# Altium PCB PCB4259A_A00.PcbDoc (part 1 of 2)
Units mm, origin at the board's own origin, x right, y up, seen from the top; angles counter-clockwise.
Board outline 30 x 45 mm, 4 copper layers (Top Layer, Signal Layer 2, Signal Layer 3, Bottom Layer), stack 1.606 mm thick; 90 components, 88 nets, 336 pads, 378 vias.
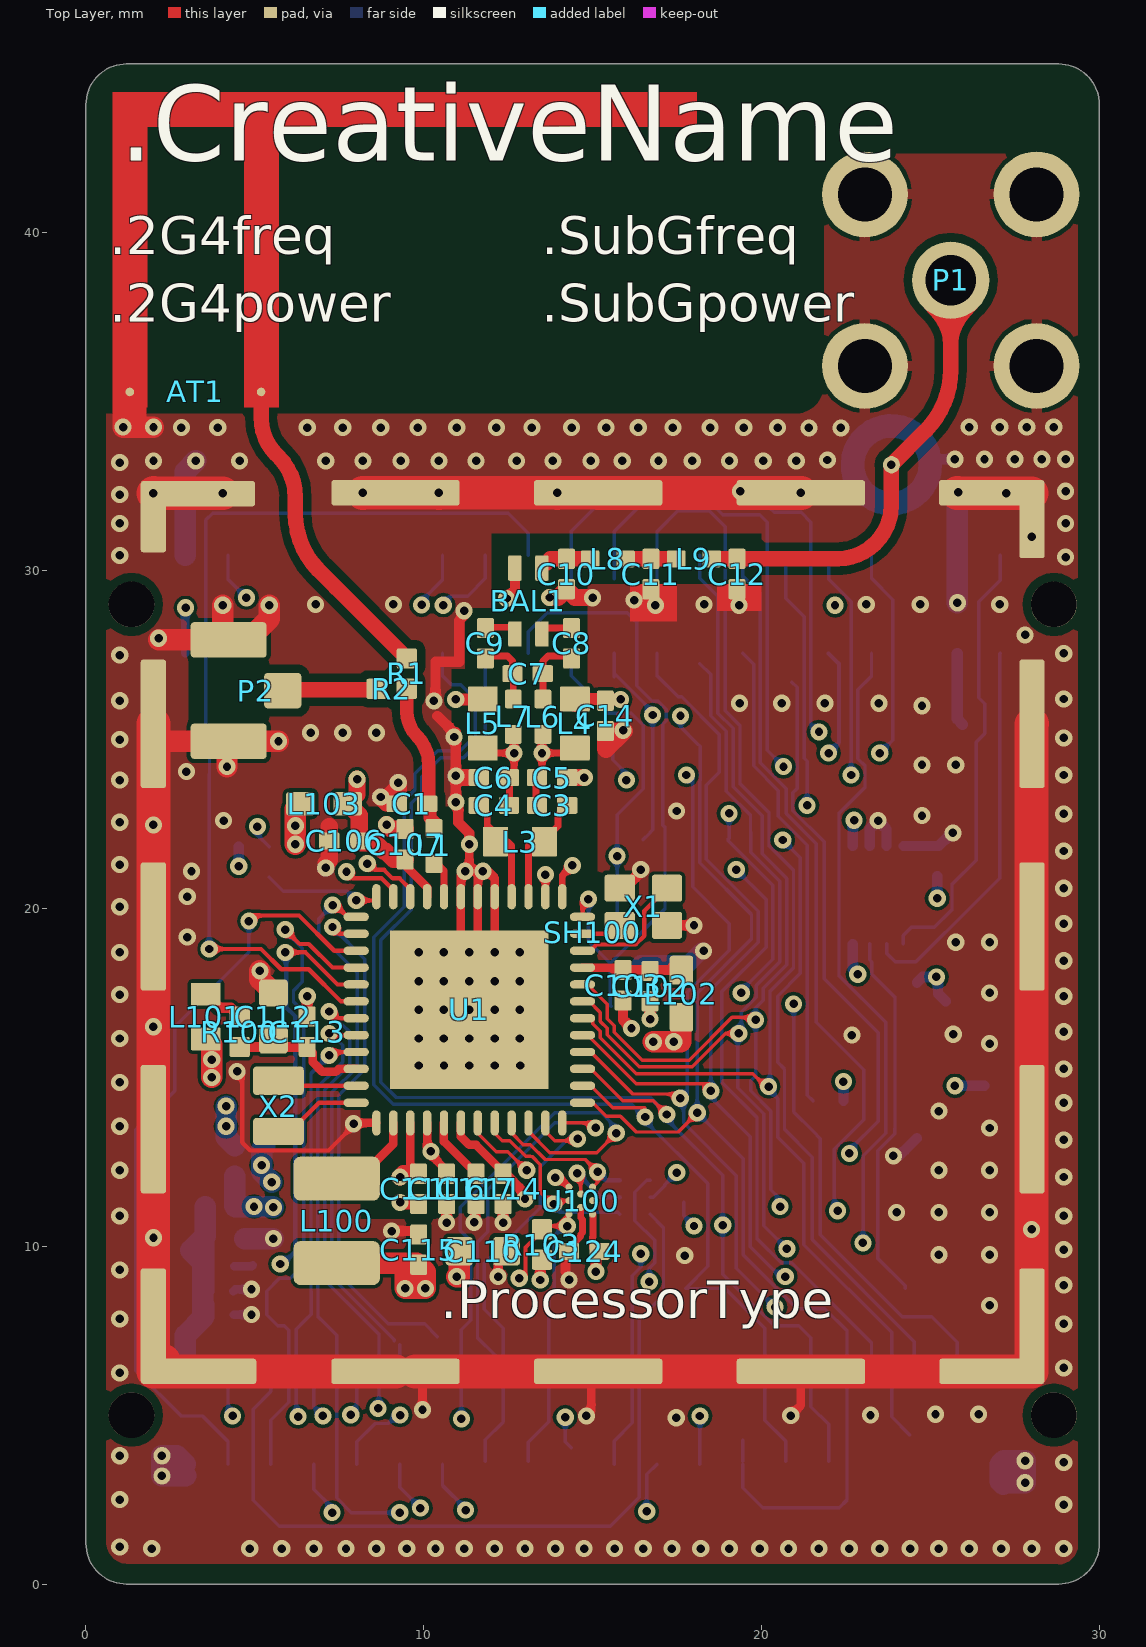
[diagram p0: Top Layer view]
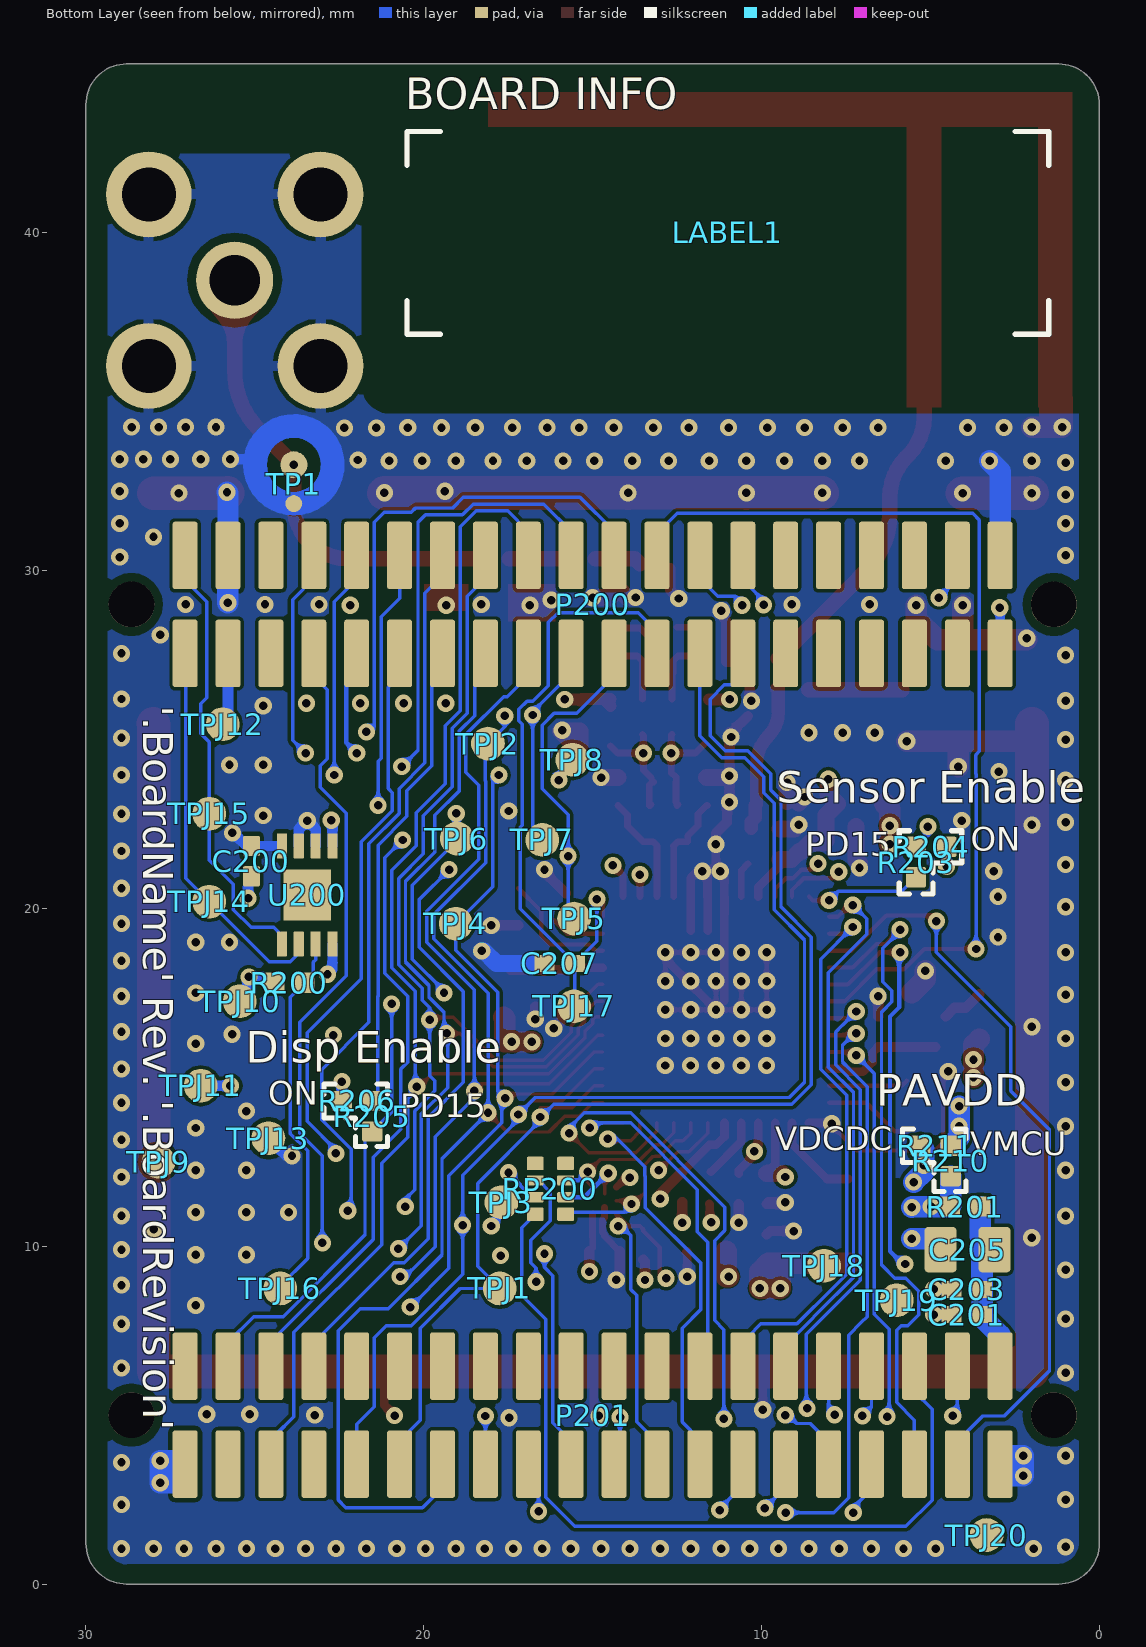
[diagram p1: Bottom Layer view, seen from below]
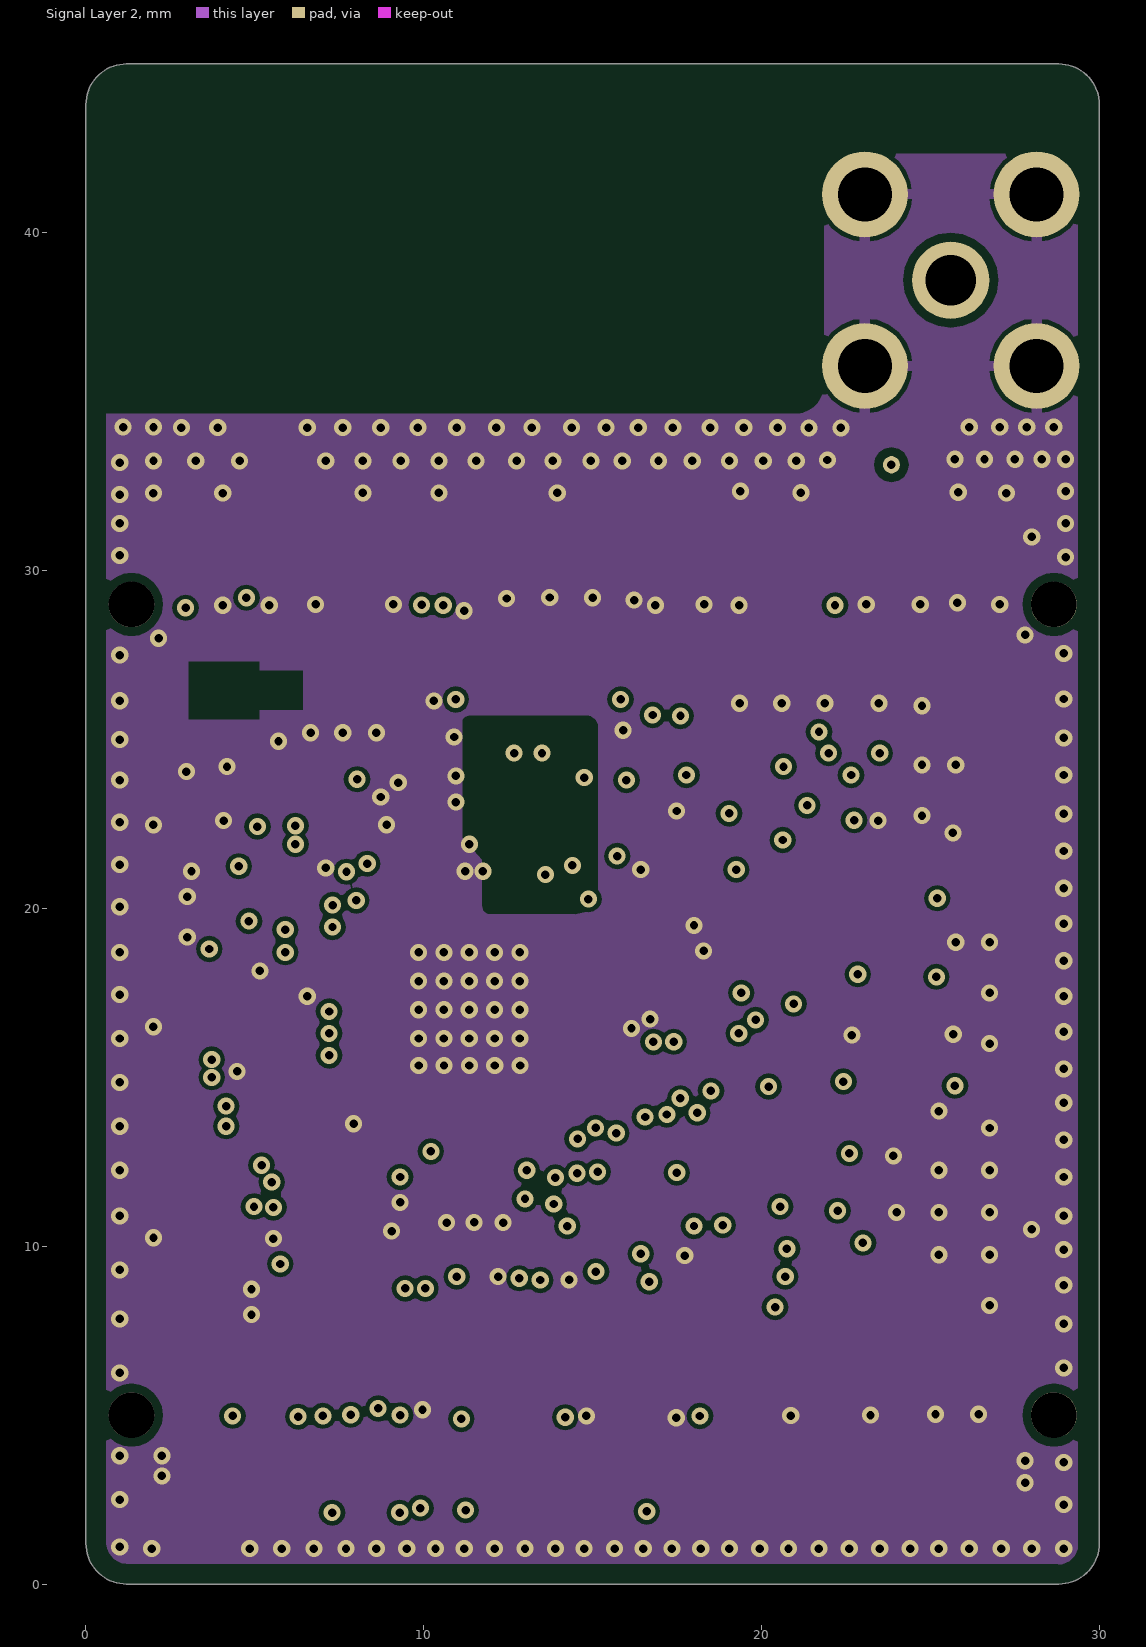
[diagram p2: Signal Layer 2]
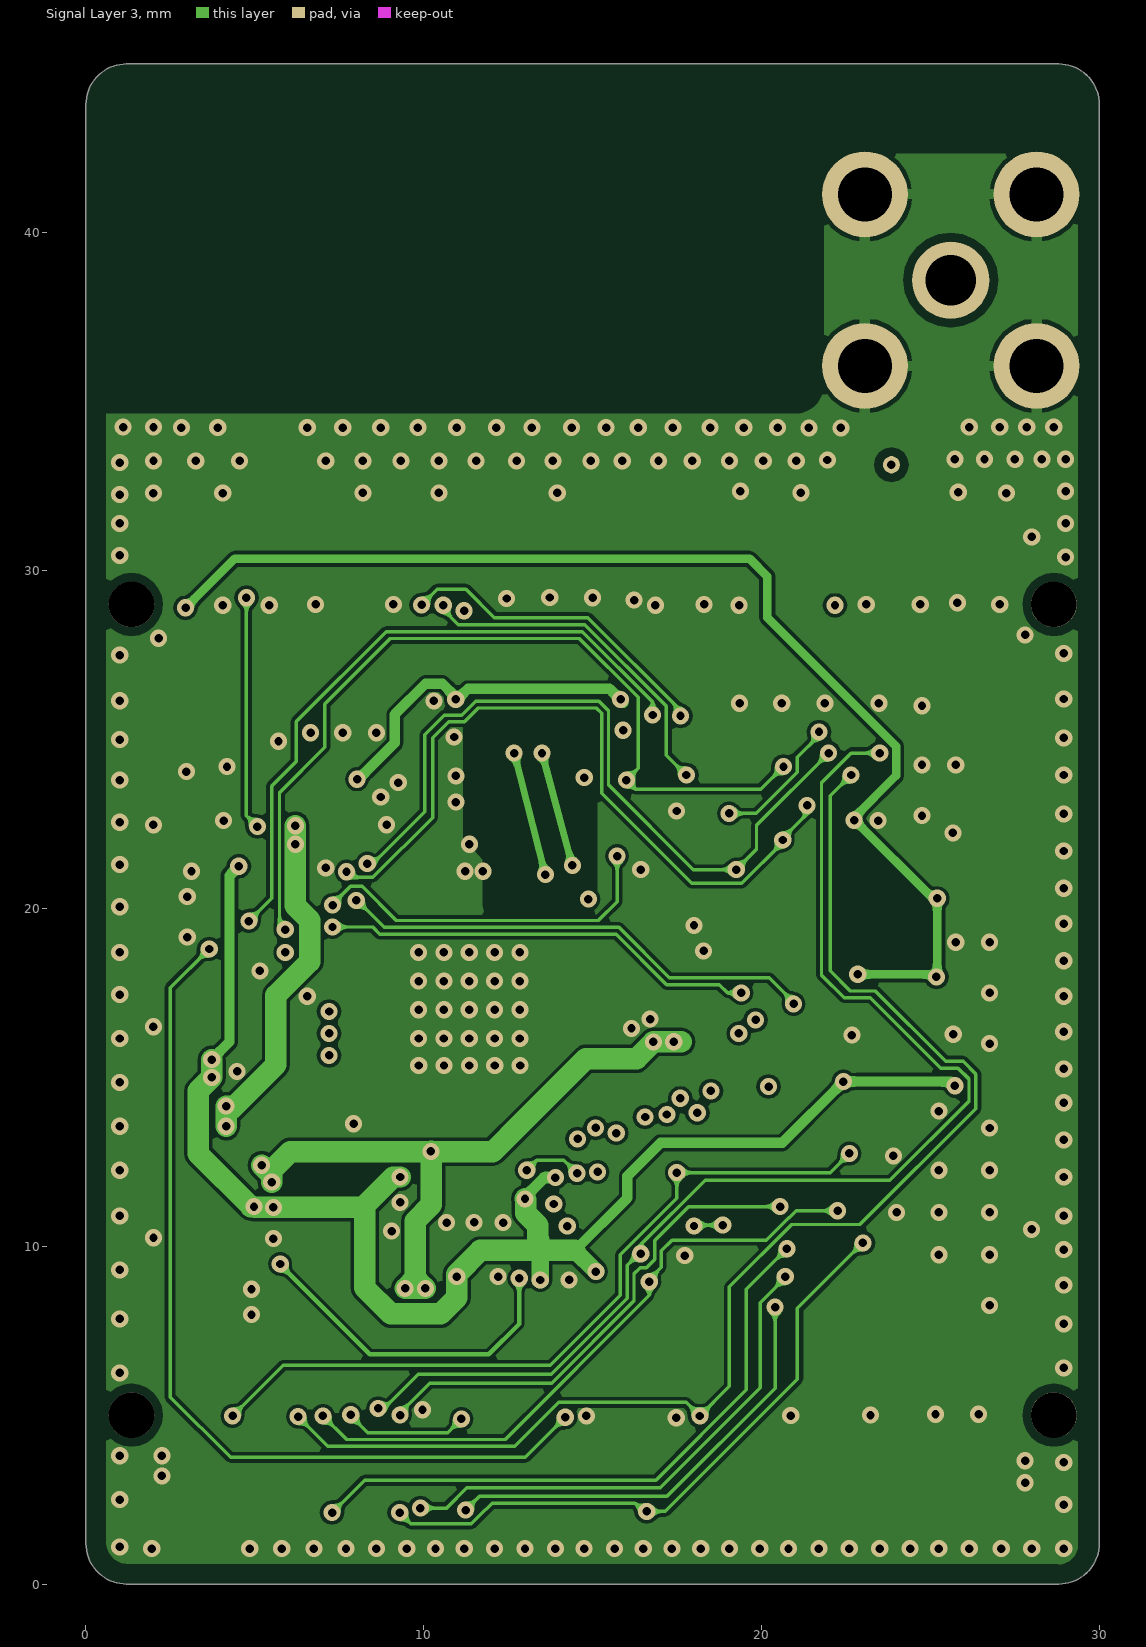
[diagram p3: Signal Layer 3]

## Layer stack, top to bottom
Top Solder: solder mask 0.01, Solder Resist, Dk 3.5
Top Layer: signal copper 0.035
Dielectric 1: core 0.3, FR-4, Dk 4.2
Signal Layer 2: signal copper 0.018
Dielectric 3: prepreg 0.9, Dk 4.2
Signal Layer 3: signal copper 0.018
Dielectric 2: core 0.3, FR-4, Dk 4.2
Bottom Layer: signal copper 0.035
Bottom Solder: solder mask 0.01, Solder Resist, Dk 3.5

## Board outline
0,1.2 ccw(c1.2,1.2) 1.2,0 28.8,0 ccw(c28.8,1.2) 30,1.2 30,43.8 ccw(c28.8,43.8) 28.8,45 1.2,45 ccw(c1.2,43.8) 0,43.8

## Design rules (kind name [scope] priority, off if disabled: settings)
Clearance Clearance_to_Holes [InPadClass('NPTH')] p1: gap=0.254
Clearance Clearance_50Ohm [InNetClass('50Ohm') or InNet('50R_*')] p2: gap=0.25
Clearance Clerance_Polygon_GND3 [InNamedPolygon('GND_3')] p3: gap=0.127
Clearance Clerance_Polygon_GND2 [InNamedPolygon('GND_2')] p4: gap=0.127
Clearance Clerance_Polygon_GND1 [InNamedPolygon('GND_L2')] p5: gap=0.127
Clearance Clerance_Polygon_GND4 [InNamedPolygon('GND_4')] p6: gap=0.127
Clearance Clearance_General [All] p7: gap=0.102
ComponentClearance [All] p1: gap=0.2 collisioncheckmode=3 verticalgap=0.254 showdistances=FALSE
HoleToHoleClearance HoleToHoleClearance_ANT1toPAD [Incomponent ('ANT1') vs ISpad] p1: gap=0 allowstackedmicrovias=TRUE
HoleToHoleClearance HoleToHoleClearance_U1toVIA_1 [InComponent ('U1') vs IsVia] p2: gap=0 allowstackedmicrovias=TRUE
HoleToHoleClearance [All] p3: gap=0.254 allowstackedmicrovias=TRUE
MinimumSolderMaskSliver [All] p1: minsoldermaskwidth=0.102
PolygonConnect PolygonConnect_SH100 [InComponent('SH100')] p1: connectstyle=Direct reliefconductorwidth=0.254 reliefentries=4 polygonreliefangle="90 Angle" airgapwidth=0.127
PolygonConnect PolygonConnect_P1 [InComponent('P1')] p2: connectstyle=Relief reliefconductorwidth=0.305 reliefentries=4 polygonreliefangle="90 Angle" airgapwidth=0.127
PolygonConnect Polygon_VIA_Connect [IsVia] p3: connectstyle=Direct reliefconductorwidth=0.254 reliefentries=4 polygonreliefangle="90 Angle" airgapwidth=0.254
PolygonConnect PolygonConnect_General [All] p4: connectstyle=NoConnect reliefconductorwidth=0.254 reliefentries=4 polygonreliefangle="90 Angle" airgapwidth=0.127
RoutingVias [All] p1: holewidth=0.25 width=0.508 viastyle="Through Hole" minholewidth=0.25 minwidth=0.508 maxholewidth=1 maxwidth=1.5
SilkToSilkClearance [All] p1: silktosilkclearance=0.102
SilkToSolderMaskClearance [IsPad] p1: minsilkscreentomaskgap=0.102 clearancetoexposedcopper=TRUE
SolderMaskExpansion [All] p1: expansion=0.051
Width [All] p1: maxlimit=5.08 minlimit=0.102 preferedwidth=0.127
25 further rules are at their usual default settings.

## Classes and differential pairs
pad class NPTH: P200-M1 P200-M2 P201-M1 P201-M2

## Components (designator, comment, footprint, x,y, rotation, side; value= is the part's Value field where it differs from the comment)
AT1 "INVERTED_F" ANT_INV_F_2.4_GHZ_17.3MM_MIR 0.79,34.84 r0 top locked net-tie
BAL1 "ATB2012-50011" TDK_ATB2012 13.1,29.1 r270 top
C1 "1P5" C0402_L 9.65,23.1 r0 top
C3 "1P6" C0402_L 13.8,23.05 r0 top
C4 "1P6" C0402_L 12.075,23.05 r180 top
C5 "Unused" C0402_L 13.8,23.875 r0 top
C6 "Unused" C0402_L 12.075,23.875 r180 top
C7 "4P7" C0402_L 13.075,26.95 r180 top
C8 "270P" C0402_L 14.375,27.85 r270 top
C9 "270P" C0402_L 11.825,27.85 r270 top
C10 "6P2" C0402_L 14.225,29.9 r270 top
C11 "11P" C0402_L 16.725,29.9 r270 top
C12 "5P6" C0402_L 19.275,29.9 r270 top
C14 "270P" C0402_L 15.375,25.7 r270 top
C102 "100P" C0402_L 16.7,17.7 r270 top
C103 "10P" C0402_L 15.9,17.725 r270 top
C106 "220N" C0402_L 7.65,22 r180 top
C107 "10P" C0402_L 9.45,21.9 r90 top
C110 "10U" C0603_L 11.75,9.85 r0 top
C111 "1U" C0402_L 9.848,11.7 r270 top
C112 "10U" C0603_L 5.55,16.8 r90 top
C113 "10N" C0402_L 6.548,16.35 r90 top
C114 "1U" C0402_L 12.35,11.7 r270 top
C115 "4U7" C0402_L 9.85,9.9 r90 top
C116 "100N" C0402_L 10.675,11.7 r270 top
C117 "1U" C0402_L 11.55,11.7 r270 top
C124 "100N" C0402_L 14.75,9.85 r180 top
C200 "100N" C0402_L 25.1,21.4 r90 bottom
C201 "100N" C0402_L 3.925,7.975 r0 bottom
C203 "100N" C0402_L 3.925,8.725 r0 bottom
C205 "10U" C0805_L 3.9,9.9 r0 bottom
C207 "100N" C0402_L 15.975,18.375 r0 bottom
Designator16 "Comment" PCB_SPEC_4_LAYER -81.197,100.739 r0 top
L1 "1N9" COIL_0402_L 10.3,21.85 r90 top
L3 "75N" COIL_0603_L 12.85,21.975 r180 top
L4 "470N" COIL_0603_L 14.475,25.475 r270 top
L5 "470N" COIL_0603_L 11.75,25.475 r270 top
L6 "18N" COIL_0402_L 13.525,25.675 r270 top
L7 "18N" COIL_0402_L 12.65,25.675 r270 top
L8 "24N" COIL_0402_L 15.45,30.35 r180 top
L9 "24N" COIL_0402_L 18,30.35 r180 top
L100 "4U7" COIL_MUR_LQH3NP_1212 7.425,10.75 r270 top
L101 "CBF102WB" WURTH_CBF_0603 3.55,16.8 r90 top
L102 "BLM18AG601SN1" COIL_MUR_BLM18_0603 17.628,17.475 r90 top
L103 "BLM18AG601SN1" COIL_MUR_BLM18_0603 7.05,23.1 r0 top
LABEL1 "Comment" LABEL_4CORNERS_19.0X6.0 11,40 r180 bottom
P1 "SMA" TE_SMA_TH_1814832 25.6,38.6 r0 top locked
P2 "U.FL" HIROSE_U.FL-R-SMT-1 4.225,26.45 r270 top
P200 "SOCKET_2X20_1.27MM_SMD" SAM_SFC-120-T2-D-A-2X20_SNUM 15,29 r0 bottom locked
P201 "SOCKET_2X20_1.27MM_SMD" SAM_SFC-120-T2-D-A-2X20_SNUM 15,5 r0 bottom locked
R1 "0R" R0402_L 9.5,26.95 r90 top
R2 "0R" R0402_L 9.05,26.5 r180 top
R100 "1R" R0402_L 4.55,16.35 r270 top
R103 "330K" R0402_L 13.5,10.05 r90 top
R200 "10K" R0402_L 23.978,17.8 r0 bottom
R201 "0R" R0402_L 3.975,11.175 r0 bottom
R203 "0R" R0402_L 5.425,21.375 r90 bottom
R204 "0R" R0402_L 4.975,21.825 r0 bottom
R205 "0R" R0402_L 21.525,13.85 r90 bottom
R206 "0R" R0402_L 21.975,14.3 r180 bottom
R210 "0R" R0402_L 4.4,12.525 r270 bottom
R211 "0R" R0402_L 4.85,12.975 r0 bottom
RP200 "100R" RES_MNR04-8 16.25,11.7 r90 bottom
SH100 "RF_SHIELD_FRAME_BMI-S-203-F" RF_SHIELD_FRAME_BMI-S-203-F_PCB4100 15,19.3 r0 top locked
TP1 "RF_TEST_POINT" "TP_INGUN_50_OHM_CLOSED openvia" 23.845,33.135 r180 bottom locked
TPJ1 "TPJ_SMD" TP_1.0_SMD 17.75,8.75 r90 bottom locked
TPJ2 "TPJ_SMD" TP_1.0_SMD 18.1,24.88 r90 bottom locked
TPJ3 "TPJ_SMD" TP_1.0_SMD 17.7,11.3 r90 bottom locked
TPJ4 "TPJ_SMD" TP_1.0_SMD 19.05,19.55 r90 bottom locked
TPJ5 "TPJ_SMD" TP_1.0_SMD 15.55,19.7 r90 bottom locked
TPJ6 "TPJ_SMD" TP_1.0_SMD 19.02,22.07 r90 bottom locked
TPJ7 "TPJ_SMD" TP_1.0_SMD 16.49,22.03 r90 bottom locked
TPJ8 "TPJ_SMD" TP_1.0_SMD 15.6,24.4 r90 bottom locked
TPJ9 "TPJ_SMD" TP_1.0_SMD 27.85,12.5 r90 bottom locked
TPJ10 "TPJ_SMD" TP_1.0_SMD 25.45,17.25 r90 bottom locked
TPJ11 "TPJ_SMD" TP_1.0_SMD 26.6,14.75 r90 bottom locked
TPJ12 "TPJ_SMD" TP_1.0_SMD 25.95,25.45 r90 bottom locked
TPJ13 "TPJ_SMD" TP_1.0_SMD 24.6,13.2 r90 bottom locked
TPJ14 "TPJ_SMD" TP_1.0_SMD 26.35,20.2 r90 bottom locked
TPJ15 "TPJ_SMD" TP_1.0_SMD 26.35,22.8 r90 bottom locked
TPJ16 "TPJ_SMD" TP_1.0_SMD 24.25,8.75 r90 bottom locked
TPJ17 "TPJ_SMD" TP_1.0_SMD 15.55,17.1 r90 bottom locked
TPJ18 "TPJ_SMD" TP_1.0_SMD 8.15,9.42 r90 bottom locked
TPJ19 "TPJ_SMD" TP_1.0_SMD 6,8.4 r90 bottom locked
TPJ20 "TPJ_SMD" TP_1.0_SMD 3.34,1.45 r90 bottom locked
U1 "EFR32FG14P233F256GM48" QFN48_M050_SQ7.0_EP_SL_L 11.35,17 r180 top
U100 "MX25R8035F" BGA8_M040_1.24x1.75_WLCSP 14.648,11.35 r180 top
U200 "24AA024" TDFN8_M050_2.0x3.0_EP 23.45,20.4 r0 bottom
X1 "38.400 MHz" X_SSS_DSX211SH_2.05X1.65-4 16.5,20.05 r0 top
X2 "32.768 kHz" X_MCS_CM8V-T1A 5.698,14.15 r90 top

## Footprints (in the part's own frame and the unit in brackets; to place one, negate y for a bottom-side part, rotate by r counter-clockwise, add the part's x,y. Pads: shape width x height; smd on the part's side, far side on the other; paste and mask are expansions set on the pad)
ANT_INV_F_2.4_GHZ_17.3MM_MIR [mil] "Antenna inverted F, 2.4 GHz, 17.3 mm (MIR)"
  round 10 smd paste-5 mask-5: 1(173,17.72) 2(20.01,17.72)
  Top Layer region: 0.36,367.2 681,367.2 681,327.07 193.36,327.07 193.36,0 153.36,0 153.36,327.07 40.36,327.07 40.36,0 20.36,0 0.36,0
BGA8_M040_1.24x1.75_WLCSP [mm] "BGA, 8 pin. U100"
  round 0.21 smd mask+0.051: A1(-0.35,0.4) A3(0.35,0.4) B2(0,0.2) C1(-0.35,0) C3(0.35,0) D2(0,-0.2) E1(-0.35,-0.4) E3(0.35,-0.4)
  body extent -0.63,-0.89 0.63,0.88, height 0.52
C0402_L [mm] "Chip Capacitor, 2-Leads, Body 1.0x0.5mm, IPC High Density"
  rrect20% 0.6x0.5 smd mask+0.051: 1(-0.45,0) 2(0.45,0)
  body extent -0.5,-0.25 0.5,0.25, height 0.6
C0603_L [mm] "Capacitor, 0603, High Density (C)"
  rrect25% 0.8x0.85 smd: 1(-0.7,0) 2(0.7,0)
  body extent -0.88,-0.48 0.87,0.48, height 0.95
C0805_L [mm] "Capacitor, 0805"
  rrect25% 0.95x1.35 smd: 1(-0.8,0) 2(0.8,0)
  body extent -1.1,-0.72 1.1,0.72, height 1.45
COIL_0402_L [mm] "COIL_0402_L"
  rrect20% 0.55x0.5 smd mask+0.051: 1(-0.525,0) 2(0.525,0)
  body extent -0.5,-0.25 0.5,0.25, height 0.6
COIL_0603_L [mm] "COIL 0603_L (= L0603_0.8_L)"
  rrect10% 0.75x0.88 smd: 1(-0.725,0) 2(0.725,0)
  body extent -0.8,-0.4 0.8,0.4, height 0.8
COIL_MUR_BLM18_0603 [mm] "COIL_MUR_BLM18P_0603"
  rrect25% 0.85x0.7 smd mask+0.051: 1(-0.7,0) 2(0.7,0)
  body extent -0.88,-0.48 0.87,0.48, height 0.95
COIL_MUR_LQH3NP_1212 [mm] "COIL_MUR_LQH3NP_1212"
  rrect30% 1.3x2.55 smd mask+0.051: 1(-1.25,0) 2(1.25,0)
  body extent -1.6,-1.6 1.6,1.6, height 1.5
HIROSE_U.FL-R-SMT-1 [mm] "COAX_HIROSE_U.FL_CL331-0471"
  rrect20% 1.05x1.1 smd mask+0.051: 1(0,1.6)
  rrect20% 1.05x2.25 smd mask+0.051: 2(-1.5,0) 3(1.5,0)
  Top Layer pour cut-out: -0.85,0.9 0.85,0.9 0.85,0.9 0.85,-1.2 -0.85,-1.2 -0.85,-1.2
  body extent -1.3,-1.55 1.3,1.3, height 0.9
LABEL_4CORNERS_19.0X6.0 [mm]
  silkscreen extent -9.5,-3 9.5,3
PCB_SPEC_4_LAYER [mm]
QFN48_M050_SQ7.0_EP_SL_L [mm] "QFN48_M050_SQ7.0_EP, SiLabs, High Density (C)"
  oval 0.75x0.25 smd: 1(-3.35,2.75) 2(-3.35,2.25) 3(-3.35,1.75) 4(-3.35,1.25) 5(-3.35,0.75) 6(-3.35,0.25) 7(-3.35,-0.25) 8(-3.35,-0.75) 9(-3.35,-1.25) 10(-3.35,-1.75) 11(-3.35,-2.25) 12(-3.35,-2.75) 25(3.35,-2.75) 26(3.35,-2.25) 27(3.35,-1.75) 28(3.35,-1.25) 29(3.35,-0.75) 30(3.35,-0.25) 31(3.35,0.25) 32(3.35,0.75) 33(3.35,1.25) 34(3.35,1.75) 35(3.35,2.25) 36(3.35,2.75)
  oval 0.25x0.75 smd: 13(-2.75,-3.35) 14(-2.25,-3.35) 15(-1.75,-3.35) 16(-1.25,-3.35) 17(-0.75,-3.35) 18(-0.25,-3.35) 19(0.25,-3.35) 20(0.75,-3.35) 21(1.25,-3.35) 22(1.75,-3.35) 23(2.25,-3.35) 24(2.75,-3.35) 37(2.75,3.35) 38(2.25,3.35) 39(1.75,3.35) 40(1.25,3.35) 41(0.75,3.35) 42(0.25,3.35) 43(-0.25,3.35) 44(-0.75,3.35) 45(-1.25,3.35) 46(-1.75,3.35) 47(-2.25,3.35) 48(-2.75,3.35)
  rrect50% 1.9x1.9 on Top Paste mask-0.805: 49(-1.15,1.15) 49(-1.15,-1.15) 49(1.15,1.15) 49(1.15,-1.15)
  rect 4.7x4.7 smd paste-4.7: 49(0,0)
  body extent -3.5,-3.5 3.5,3.5, height 0.9
R0402_L [mm] "Chip Resistor, 2-Leads, Body 1.0x0.5mm, IPC High Density"
  rrect20% 0.6x0.6 smd mask+0.051: 1(-0.45,0) 2(0.45,0)
  body extent -0.5,-0.25 0.5,0.25, height 0.6
RES_MNR04-8 [mm] "Chip resistor network 8pin"
  rrect20% 0.4x0.5 smd mask+0.051: 1(-0.75,-0.45) 4(0.75,-0.45) 5(0.75,0.45) 8(-0.75,0.45)
  rrect20% 0.3x0.5 smd mask+0.051: 2(-0.25,-0.45) 3(0.25,-0.45) 6(0.25,0.45) 7(-0.25,0.45)
  body extent -1,-0.4 1,0.4, height 0.5
RF_SHIELD_FRAME_BMI-S-203-F_PCB4100 [mm] "RF_SHIELD_FRAME_BMI-S-203-F"
  rrect20% 0.75x3.8 smd paste+0 mask+0.05: 1(-13.005,-5.835) 1(-13.005,0.165) 1(-13.005,6.165) 1(13.005,-5.835) 1(13.005,0.165) 1(13.005,6.165)
  rrect20% 0.75x3.4 smd paste+0 mask+0.05: 1(-13.005,-11.659) 1(13.005,-11.659)
  rrect20% 0.75x2.1 smd paste+0 mask+0.05: 1(-13.005,12.294)
  oval 0.75x0.254 smd paste+0 mask+0.05: 1(-13.004,12.994) 1(12.994,12.994) 1(12.994,12.994) 1(12.994,12.994)
  rrect20% 3.375x0.75 smd paste+0 mask+0.05: 1(-11.684,12.979)
  rrect20% 3.4x0.75 smd paste+0 mask+0.05: 1(-11.659,-13.005)
  rrect20% 3.8x0.75 smd paste+0 mask+0.05: 1(-5.835,-13.005) 1(-5.835,13.005) 1(0.165,-13.005) 1(0.165,13.005) 1(6.165,-13.005) 1(6.165,13.005)
  rrect20% 3.1x0.75 smd paste+0 mask+0.05: 1(11.811,-13.005)
  rrect20% 3.125x0.75 smd paste+0 mask+0.05: 1(11.811,13.005)
  rrect20% 0.75x2.3 smd paste+0 mask+0.05: 1(13.005,12.217)
  body extent -13.3,-13.3 13.3,13.3, height 5.5
SAM_SFC-120-T2-D-A-2X20_SNUM [mm]
  rrect20% 0.74x2 smd mask+0.05: 1(-12.065,1.45) 2(-12.065,-1.45) 3(-10.795,1.45) 4(-10.795,-1.45) 5(-9.525,1.45) 6(-9.525,-1.45) 7(-8.255,1.45) 8(-8.255,-1.45) 9(-6.985,1.45) 10(-6.985,-1.45) 11(-5.715,1.45) 12(-5.715,-1.45) 13(-4.445,1.45) 14(-4.445,-1.45) 15(-3.175,1.45) 16(-3.175,-1.45) 17(-1.905,1.45) 18(-1.905,-1.45) 19(-0.635,1.45) 20(-0.635,-1.45) 21(0.635,1.45) 22(0.635,-1.45) 23(1.905,1.45) 24(1.905,-1.45) 25(3.175,1.45) 26(3.175,-1.45) 27(4.445,1.45) 28(4.445,-1.45) 29(5.715,1.45) 30(5.715,-1.45) 31(6.985,1.45) 32(6.985,-1.45) 33(8.255,1.45) 34(8.255,-1.45) 35(9.525,1.45) 36(9.525,-1.45) 37(10.795,1.45) 38(10.795,-1.45) 39(12.065,1.45) 40(12.065,-1.45)
  round 1.35 hole 1.35 unplated paste-5.563 mask-5.563: M1(13.652,0) M2(-13.652,0)
  body extent -14.65,-1.58 14.65,2.25, height 4.57
TDFN8_M050_2.0x3.0_EP [mm] "TDFN8_M050_2.0x3.0_EP"
  rrect20% 0.3x0.75 smd mask+0.051: 1(-0.75,-1.45) 2(-0.25,-1.45) 3(0.25,-1.45) 4(0.75,-1.45) 5(0.75,1.45) 6(0.25,1.45) 7(-0.25,1.45) 8(-0.75,1.45)
  rect 1.4x1.5 smd mask+0.051: 9(0,0)
  body extent -1,-1.5 1,1.5, height 1
TDK_ATB2012 [mm]
  rrect20% 0.75x0.4 smd: 1(-0.975,0.4) 2(-0.975,-0.4) 3(0.975,-0.4) 4(0.975,0.4)
  body extent -1,-0.6 1,0.6, height 1.21
TE_SMA_TH_1814832 [mm]
  round 2.286 hole 1.5: 1(0,0)
  round 2.54 hole 1.6: 2(-2.54,-2.54) 3(2.54,-2.54) 4(2.54,2.54) 5(-2.54,2.54)
  body extent -3.2,-3.2 3.2,3.2, height 9.5
TP_1.0_SMD [mm] "Test Point, 1.0 mm, SMD"
  round 1 smd paste-0.501: 1(0,0)
"TP_INGUN_50_OHM_CLOSED openvia" [mm] "TP_INGUN_50_OHM_CLOSED"
  round 0.8 / inner round 0.508 / far side round 0.508 hole 0.25 mask+0: 1(0,0)
  round 0.5 smd paste-0.255 mask-0.41: 2(0,-1.15)
  Top Layer lines w0.7: 0,-1.15 cw(c0,0) -1.15,0 cw(c0,0) 0,-1.15
WURTH_CBF_0603 [mm] "COIL_WURTH_CBF_0603_L (= L0603_0.8_L)"
  rrect10% 0.67x0.88 smd: 1(-0.665,0) 2(0.665,0)
  body extent -0.87,-0.48 0.87,0.48, height 0.95
X_MCS_CM8V-T1A [mm] "Crystal MCS CM8V-T1A (2 pin)"
  rrect25% 0.8x1.5 smd paste-0.15 mask+0.051: 1(-0.75,0)
  rrect25% 0.85x1.5 smd paste-0.15 mask+0.051: 2(0.75,0)
  body extent -1,-0.6 1,0.6, height 0.97
X_SSS_DSX211SH_2.05X1.65-4 [mm] "X_SSS_DSX211SH_2.05X1.65-4"
  rrect20% 0.9x0.8 smd mask+0.051: 1(-0.7,-0.55) 2(0.7,-0.55) 3(0.7,0.55) 4(-0.7,0.55)
  body extent -1.07,-0.87 1.07,0.87, height 0.5

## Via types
v1: diameter 0.508, hole 0.25, Top Layer to Bottom Layer, tented both sides, 376 vias
v2: diameter 0.5, hole 0.25, Top Layer to Bottom Layer, tented both sides, 2 vias

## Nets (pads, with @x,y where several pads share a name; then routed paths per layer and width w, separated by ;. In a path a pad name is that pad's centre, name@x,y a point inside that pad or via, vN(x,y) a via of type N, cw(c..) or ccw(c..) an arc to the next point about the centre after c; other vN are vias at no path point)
3V3: C200.1 P200.1 R200.2 TPJ10.1 U200.1 U200.8 | length 40.6
  Signal Layer 3 w0.254: v1(2.95,28.9) 4.4,30.35 19.65,30.35 20.171,29.829 20.171,28.612 23.983,24.8 23.983,23.933 22.738,22.688 v1(22.738,22.613) 22.754,22.613 25.067,20.3 v1(25.2,20.3) v1@25.2,18 ; v1(22.85,18.05) 25.15,18.05 v1@25.163,18.037
  Bottom Layer w0.254: P200.1@2.935,27.55 2.935,28.885 v1(2.95,28.9)
  Bottom Layer w0.305: U200.8@22.7,18.95 22.7,18.2 v1(22.85,18.05) ; U200.1@22.7,21.85 22.7,22.575 v1(22.738,22.613) ; R200.2@24.6,17.8 24.775,17.975 v1(25.175,17.975) 25.225,17.925 25.225,17.475 TPJ10.1@25.45,17.25 ; v1(25.2,20.3) C200.1@25.2,20.95
5V: P200.37 TPJ12.1 | length 2.2
  Bottom Layer w0.33: P200.37@25.795,27.55 25.795,25.605 TPJ12.1@25.95,25.45
50R_IFA: AT1.1 R1.2 | length 9.3
  Top Layer w0.457: AT1.1@5.184,35.29 5.184,34.54 ccw(c6.752,34.54) 5.643,33.432 ; 5.706,33.369 cw(c4.51,32.175) 6.2,32.175 6.2,31.69 ccw(c8.59,31.69) 6.9,30 7.4,29.5 R1.2@9.5,27.4
50R_R1: C1.2 L1.2 R1.1 R2.1 | length 4.3
  Top Layer w0.396: R1.1@9.5,26.5 9.5,25.824 ccw(c10.524,25.824) 9.8,25.1 cw(c8.955,24.255) 10.15,24.255 C1.2@10.15,23.125 ; C1.2@10.16,23.089 10.185,23.063 10.185,22.682 10.3,22.568 L1.2@10.3,22.375
50R_SMA: C12.1 L9.1 P1.1 TP1.1 | length 13.6
  Top Layer w0.457: L9.1@18.525,30.35 C12.1@19.275,30.35 22.275,30.35 ccw(c22.243,31.952) 23.845,31.92 ; 23.845,31.985 cw(c22.243,31.952) 23.845,31.92 ; P1.1@25.6,38.6 25.6,35.942 cw(c23.06,35.942) 24.856,34.146 TP1.1@23.845,33.135 23.845,31.92
50R_UFL: P2.1 R2.2 | length 2.8
  Top Layer w0.396: P2.1@5.825,26.45 P2.1@5.85,26.475
  Top Layer w0.457: P2.1@5.85,26.475 R2.2@8.6,26.475
BOARD_ID_SCL: P200.39 TPJ14.1 U200.6 | length 11.4
  Bottom Layer w0.102: U200.6@23.7,18.95 23.7,18.676 23.953,18.423 24.573,18.423 TPJ14.1@26.35,20.2 27.05,20.9 27.05,27.535 P200.39@27.065,27.55
BOARD_ID_SDA: P200.40 TPJ15.1 U200.5 | length 13.2
  Bottom Layer w0.102: U200.5@24.2,18.95 24.2,19.2 24.438,19.438 25.113,19.438 25.638,19.963 25.638,20.713 26.35,21.425 TPJ15.1@26.35,22.8 26.35,24.927 26.602,25.18 26.602,26.061 26.425,26.238 26.425,29.075 27.065,29.715 P200.40@27.065,30.45
BOARD_ID_WP: R200.1 TPJ16.1 U200.7 | length 11.1
  Bottom Layer w0.102: U200.7@23.2,18.95 23.2,18.481 23.266,18.415 23.266,18.059 23.95,17.376 23.95,13.475 23.948,13.473 23.948,13.335 23.437,12.825 23.437,9.637 24.25,8.825 TPJ16.1@24.25,8.75
FLASH_MISO: RP200.1 U1.44 U100.C3 | length 5.7
  Top Layer w0.102: U1.44@12.1,13.65 12.098,13.35 12.325,13.123 12.55,13.123 13.015,12.658 13.153,12.658 13.154,12.656 13.216,12.656 13.454,12.418 13.454,12.082 13.448,12.075 13.448,11.6 v1@13.648,11.4 ; v1(13.85,11.25) 13.95,11.35 U100.C3@14.298,11.35
  Bottom Layer w0.102: v1@13.824,11.224 14.045,11.003 15.747,11.003 RP200.1@15.8,10.95
FLASH_MOSI: RP200.2 U1.43 U100.D2 | length 6.2
  Top Layer w0.102: U1.43@11.598,13.65 11.598,13.35 12.148,12.8 12.484,12.8 13.034,12.25 v1(13.048,12.25) ; v1(14.538,12.161) 14.648,12.051 U100.D2@14.648,11.55
  Signal Layer 3 w0.102: v1(13.048,12.25) 13.348,12.55 14.149,12.55 v1(14.538,12.161)
  Bottom Layer w0.127: v1(14.538,12.161) 15.249,11.45 RP200.2@15.8,11.45
FLASH_SCLK: RP200.3 U1.45 U100.E1 | length 4.6
  Top Layer w0.102: U1.45@12.6,13.65 12.598,13.362 12.95,13.01 13.15,13.01 13.593,12.567 14.781,12.567 v1(15.148,12.2) 15.148,11.9 U100.E1@14.998,11.75
  Bottom Layer w0.127: v1(15.148,12.2) 15.398,11.95 RP200.3@15.8,11.95
FLASH_SCS: P201.17 R103.2 U1.29 U100.A3 | length 32.5
  Top Layer w0.127: v1(5.9,18.7) 6.498,18.7 7.448,17.75 U1.29@8,17.75 ; v1(12.826,9.05) 13.015,9.24 13.015,9.965 13.5,10.45 R103.2@13.5,10.5 13.597,10.597 v1@14.151,10.597 ; v1(14.248,10.597) v1@14.151,10.597 ; U100.A3@14.298,10.95 14.048,10.7 v1@14.151,10.597
  Signal Layer 3 w0.127: v1(5.75,9.475) 5.75,9.45 8.4,6.8 11.925,6.8 12.826,7.7 v1(12.826,9.05)
  Bottom Layer w0.102: P201.17@13.095,3.635 13.095,4.195 13.7,4.8 13.7,6.438 ; 13.695,6.443 13.7,6.438 ; v1(14.248,10.597) 14.145,10.597 13.869,10.321 13.869,8.719 13.7,8.55 13.7,6.438
  Bottom Layer w0.127: v1@5.775,9.425 5.787,9.438 6.2,9.85 6.2,16.8 5.928,17.072 5.928,18.653 5.926,18.651 5.9,18.677 v1(5.9,18.7)
GND: AT1.2 BAL1.2 C1.1 C5.2 C6.2 C10.2 C11.2 C12.2 C14.2 C102.2 C103.2 C106.2 C107.2 C110.2 C111.2 C112.2 C113.2 C114.2 C115.2 C116.2 C117.2 C124.2 C200.2 C201.2 C203.2 C205.2 C207.2 P1.2 P1.3 P1.4 P1.5 P2.2 P2.3 P200.2 P200.38 P201.1 P201.39 SH100.1 TP1.2 TPJ13.1 U1.17 U1.18 U1.19 U1.37 U1.49@11.35,17 U100.B2 U200.2 U200.3 U200.4 X1.2 X1.4 | length 177.5
  Top Layer w0.127: v1(4.475,15.175) 4.625,15.025 4.625,13.075 4.865,12.835 7.183,12.835 v1@7.998,13.65 ; v1(9.848,18.7) v1(9.848,17.85) 9.848,17.75 v1(9.848,17) v1(10.598,17) ; v1(10.598,17.85) v1(10.598,17) ; v1(11.348,17.85) v1(11.348,17) ; v1(11.348,18.7) 11.898,18.7 U1.49@12.098,18.5 ; v1(12.098,18.7) 12.648,18.7 U1.49@12.848,18.5 ; v1(12.848,17) v1(12.098,17) U1.49@11.35,17 v1(11.348,17) ; v1(12.848,17.85) U1.49@12.848,18.5 ; v1(12.848,18.7) U1.49@12.848,18.5 ; v1(10.598,17) v1(11.348,17)
  Top Layer w0.203: v1@11.125,21.175 v1@11.2,21.1 ; C124.2@14.198,9.85 14.648,10.3 14.648,10.351 14.705,10.407 14.705,10.786 14.648,10.843 U100.B2@14.648,11.15
  Top Layer w0.254: v1@7.998,13.65 U1.37@8.598,13.65 ; SH100.1@9.165,6.295 9.756,6.295 9.963,6.088 v1(9.963,5.159) ; 11.098,19.848 U1.19@11.098,20.35 ; U1.49@11.1,17.25 U1.19@11.1,20.35 11.1,21 v1@11.2,21.1 ; v1(11.348,17) U1.49@12.848,18.5 ; v1@11.35,21.25 v1(11.35,21.9) ; v1(11.49,10.704) 11.538,10.752 11.538,11.238 C117.2@11.55,11.25 ; U1.49@11.598,19.348 U1.18@11.598,20.35 ; U1.18@11.6,20.35 11.6,20.95 v1(11.75,21.1) 11.9,21.1 12.1,20.9 U1.17@12.1,20.35 ; U1.49@12.098,19.348 U1.17@12.1,20.35 ; C110.2@12.198,9.85 12.238,9.81 12.2,9.772 v1(12.2,9.1) ; v1(14.816,4.979) 14.963,5.126 14.963,6.093 SH100.1@15.165,6.295 ; v1(20.863,4.988) 21.165,5.29 SH100.1@21.165,6.295
  Top Layer w0.305: v1(0.998,21.3) v1@0.998,21.35 ; C113.2@6.548,16.8 6.548,17.398 v1(6.55,17.4) ; v1(9.05,10.45) C115.2@9.747,10.45 ; C115.2@9.747,10.451 C115.2@9.848,10.35 ; v1@10.351,26.126 10.351,26.775 ; 10.35,26.776 10.35,27.3 11.05,27.3 11.05,28.525 v1@11.201,28.676 ; 10.4,25.7 v1@10.874,25.226 ; v1(10.675,10.7) C116.2@10.675,11.25 ; v1@10.928,23.178 v1@10.95,23.157 ; v1(10.95,23.15) v1@10.95,23.157 ; v1@10.951,25.226 v1@10.874,25.226 ; v1@11.35,21.25 11.5,21.1 v1(11.75,21.1) ; v1(11.35,21.9) 11.35,22.225 11.025,22.55 11.025,23.203 v1@10.95,23.278 ; C6.2@11.625,23.875 C6.2@11.625,23.875 ; v1(12.348,10.7) C114.2@12.348,11.3 ; v1(12.451,29.176) 12.7,29.426 BAL1.2@12.7,30.075 ; 14.198,9.25 C124.2@14.198,9.85 ; X1.4@15.8,20.45 16.426,21.076 v1(16.426,21.151) ; C103.2@15.9,17.1 15.9,16.7 v1(16.15,16.45) ; v1(16.701,16.726) C102.2@16.701,17.099 ; X1.2@17.2,19.5 v1(18,19.5) ; SH100.1@28,30.95 v1(28,31) ; v1@10.874,25.226 v1@10.95,25.15 ; v1@10.874,25.226 v1@10.95,25.15 ; v1@10.95,23.157 10.95,23.178 10.9,23.228 v1@10.95,23.278 ; v1@10.95,23.278 v1(10.95,23.925) v1@10.95,25.15 ; v1(9.298,11.3) 9.798,11.3 C111.2@9.848,11.25 9.348,11.25 v1(9.298,11.3)
  Top Layer w0.5: v1(10.95,23.925) 10.999,23.876 C6.2@11.625,23.875 ; v1(13.73,29.205) 13.98,29.205 C10.2@14.225,29.45 14.475,29.2 v1(15,29.2) ; C5.2@14.25,23.875 v1(14.75,23.875) ; v1(15.9,25.273) 15.922,25.273 15.948,25.248 v1@15.9,25.2 ; v1@15.9,25.2 15.4,24.7 15.375,24.725 C14.2@15.375,25.25 15.85,25.25 v1@15.9,25.2
  Top Layer w0.508: v1(7.1,21.201) 7.104,21.205 7.104,21.339 7.2,21.435 C106.2@7.2,22 7.2,22.423 ; v1(8.725,23.3) 8.9,23.125 8.9,23.25 v1@9.246,23.596 ; v1(8.9,22.476) 9.027,22.35 C107.2@9.45,22.35 ; C1.1@9.246,23.165 v1@9.246,23.596 ; v1(9.246,23.724) v1@9.246,23.596
  Top Layer w0.635: v1(2,34.25) 1.475,34.25 ; v1@2.15,27.95 P2.2@4.075,27.95 ; SH100.1@2.3,24.95 P2.3@4.225,24.95 ; v1(4.05,28.975) 4.05,28.125 P2.2@4.225,27.95 4.8,27.95 5.425,28.575 v1(5.425,28.975) ; v1(4.175,24.2) 4.175,24.85 4.15,24.875 P2.3@4.225,24.95 ; v1(5.15,18.15) 5.15,17.9 C112.2@5.55,17.5 ; v1(5.7,24.95) P2.3@4.225,24.95 ; 1.475,34.25 v1(1.1,34.25) 1.1,35.092 AT1.2@1.298,35.29 1.475,35.113 1.475,34.25
  Top Layer w1: SH100.1@1.995,6.296 SH100.1@1.995,13.465 SH100.1@1.995,19.465 ; v1(1.996,16.5) v1(1.996,22.475) SH100.1@1.995,25.465 ; SH100.1@2.006,32.305 v1(1.996,32.294) v1(4.05,32.294) ; SH100.1@2.3,6.6 1.996,6.296 SH100.1@9.165,6.295 ; v1(8.2,32.3) 8.205,32.305 SH100.1@9.165,32.305 SH100.1@10.445,32.305 ; SH100.1@9.756,6.295 SH100.1@15.165,6.295 SH100.1@21.02,6.295 ; v1(10.45,32.3) SH100.1@10.445,32.305 ; v1(13.95,32.3) SH100.1@13.955,32.305 ; SH100.1@19.324,32.3 15.17,32.3 SH100.1@15.165,32.305 SH100.1@13.955,32.305 ; SH100.1@19.428,32.3 21.16,32.3 v1(21.165,32.305) SH100.1@21.176,32.294 ; SH100.1@21.165,6.295 SH100.1@27.994,6.295 ; SH100.1@25.8,32.3 25.805,32.294 v1(27.25,32.294) SH100.1@27.994,32.294 ; SH100.1@27.994,6.296 v1(27.994,10.5) 27.994,25.454 SH100.1@28.005,25.465 ; SH100.1@10.445,32.305 SH100.1@13.955,32.305
  Signal Layer 3 w0.305: v1@15.001,29.176 v1@15.024,29.2
  Bottom Layer w0.254: C203.2@4.363,8.663 4.425,8.725 v1(4.9,8.725) ; C201.2@4.375,7.975 v1(4.9,7.975) 4.975,7.975 4.975,7.925 v1@4.963,7.913 ; C205.2@4.388,9.413 4.913,9.413 C205.2@4.938,9.438
  Bottom Layer w0.305: U200.2@23.2,21.85 23.2,22.35 v1(23.45,22.6) 23.7,22.35 U200.3@23.7,21.85 ; v1(23.901,12.676) 24.076,12.676 TPJ13.1@24.6,13.2 ; U200.4@24.2,21.85 25.2,21.85 25.25,21.85 25.638,22.238 v1(25.663,22.238) ; 24.995,33.135 25.16,33.3 v1(25.725,33.3)
  Bottom Layer w0.508: C207.2@16.425,18.375 17.85,18.375 18.218,18.743 v1(18.285,18.743)
  Bottom Layer w0.635: P201.1@2.9,3.25 2.95,3.2 v1(2.25,3.2) v1(2.25,3.8) 2.685,3.8 P201.1@2.935,3.55 ; P200.2@2.935,30.45 2.935,32.935 v1(3.25,33.25) ; C205.2@4.7,10.225 v1(5.55,10.225) ; v1(25.8,29.05) 25.8,30.445 P200.38@25.795,30.45 25.795,32.29 v1(25.825,32.319) ; P201.39@27.065,3.55 27.7,3.55 v1(27.8,3.65) ; P201.39@27.065,3.55 27.165,3.65 v1(27.8,3.65) ; P201.39@27.065,3.55 27.065,3.035 27.15,2.95 27.2,3 v1(27.8,3) v1(27.8,3.65)
  other v1: 1.948,1.05 4.848,1.05 5.798,1.05 6.748,1.05 7.698,1.05 8.598,1.05 9.498,1.05 10.348,1.05 11.198,1.05 12.098,1.05 12.998,1.05 13.898,1.05 14.748,1.05 15.648,1.05 16.498,1.05 17.348,1.05 18.198,1.05 19.048,1.05 19.948,1.05 20.798,1.05 21.698,1.05 22.598,1.05 23.498,1.05 24.398,1.05 25.248,1.05 26.148,1.05 27.098,1.05 27.998,1.05 28.948,1.05 0.998,1.1 28.948,2.35 0.998,2.5 28.948,3.6 0.998,3.8 17.475,4.925 23.225,5 25.15,5.025 26.425,5.025 0.998,6.25 28.948,6.4 28.948,7.7 0.998,7.85 26.75,8.25 28.948,8.85 14.302,9.004 0.998,9.3 17.725,9.725 25.25,9.75 26.75,9.75 28.948,9.9 2,10.25 0.998,10.9 28.948,10.9 24,11 25.25,11 26.75,11 28.948,12.05 0.998,12.25 25.25,12.25 26.75,12.25 28.948,13.15 26.75,13.5 0.998,13.55 7.923,13.625 25.25,14 28.948,14.25 0.998,14.85 28.948,15.25 9.85,15.35 10.6,15.35 11.35,15.35 12.1,15.35 12.85,15.35 26.75,16 0.998,16.15 9.848,16.15 10.598,16.15 11.348,16.15 12.098,16.15 12.848,16.15 22.675,16.25 25.675,16.275 28.948,16.35 28.948,17.4 0.998,17.45 26.75,17.5 12.098,17.85 28.948,18.45 0.998,18.7 10.598,18.7 25.75,19 26.75,19 3,19.15 28.948,19.55 0.998,20.05 3,20.35 28.948,20.6 3.125,21.1 11.225,21.1 28.948,21.7 0.998,22.55 4.075,22.6 24.75,22.75 28.948,22.8 17.485,22.884 0.998,23.8 28.948,23.95 2.975,24.05 24.75,24.25 25.75,24.25 0.998,25 28.948,25.05 10.9,25.076 6.65,25.2 7.6,25.2 8.6,25.2 24.75,26 19.351,26.076 20.599,26.076 21.875,26.076 23.475,26.076 0.998,26.15 10.3,26.144 28.948,26.2 0.998,27.5 28.948,27.55 2.149,27.999 27.8,28.1 11.194,28.812 16.856,28.976 19.335,28.975 6.8,29 9.1,29 18.3,29 23.1,29 24.7,29 27.05,29 16.226,29.126 29,30.4 1,30.45 1,31.4 29,31.4 1,32.25 19.376,32.352 29,32.35 1,33.2 2,33.25 4.55,33.25 7.1,33.25 8.2,33.25 9.325,33.25 10.45,33.25 11.55,33.25 12.75,33.25 13.825,33.25 14.95,33.25 15.875,33.25 16.95,33.25 17.95,33.25 19.05,33.25 20.05,33.25 21.025,33.25 21.95,33.275 26.6,33.3 27.5,33.3 28.3,33.3 29,33.3 21.4,34.225 22.35,34.225 2.825,34.233 3.9,34.233 6.55,34.233 7.6,34.233 8.725,34.233 9.825,34.233 10.975,34.233 12.15,34.233 13.2,34.233 14.375,34.233 15.4,34.233 16.35,34.233 17.375,34.233 18.475,34.233 19.475,34.233 20.475,34.233 26.15,34.25 27.05,34.25 27.85,34.25 28.65,34.25
LFXTAL_N: U1.36 X2.1 | length 2.7
  Top Layer w0.127: X2.1@5.698,13.4 6.048,13.4 6.898,14.25 U1.36@8,14.25
LFXTAL_P: U1.35 X2.2 | length 2.4
  Top Layer w0.127: X2.2@5.698,14.9 5.848,14.75 U1.35@8,14.75
N17603239: L1.1 U1.20 | length 1.1
  Top Layer w0.203: L1.1@10.4,21.325 10.6,21.125 U1.20@10.6,20.35
N17603622: U1.11 X1.1 | length 1.6
  Top Layer w0.127: U1.11@14.698,19.25 U1.11@14.7,19.25 15.748,19.25 X1.1@16.148,19.65
N17603629: U1.10 X1.3 | length 3.7
  Top Layer w0.127: U1.10@14.7,18.75 14.925,18.75 15.11,18.935 16.272,18.935 16.525,19.188 16.525,19.925 X1.3@17.2,20.6
N17769146: C117.1 U1.41 | length 1.8
  Top Layer w0.254: U1.41@10.598,13.65 10.598,13.1 C117.1@11.498,12.2
N17769405: L100.1 U1.38 | length 2.7
  Top Layer w0.254: L100.1@7.438,11.992 8.067,11.992 9.098,13.023 U1.38@9.1,13.65
N17853356: C102.1 C103.1 L102.2 U1.9 | length 2.9
  Top Layer w0.254: U1.9@14.7,18.25 15.65,18.25
  Top Layer w0.305: 15.65,18.175 C103.1@15.9,18.175 C102.1@16.475,18.175 ; C102.1@16.45,18.15 C102.1@16.475,18.175 ; L102.2@17.4,18.3 17.275,18.175 ; L102.2@17.425,18.175 17.275,18.175 ; C102.1@16.475,18.175 17.275,18.175
N17857389: L101.2 R100.1 | length 1.3
  Top Layer w0.305: L101.2@3.55,17.465 3.958,17.057 4.293,17.057 R100.1@4.55,16.8
N17857391: C112.1 C113.1 R100.2 U1.34 | length 3.7
  Top Layer w0.254: C113.1@6.548,15.9 6.715,15.733 6.715,15.45 6.998,15.167 7.398,15.167 7.481,15.25 U1.34@8,15.25
  Top Layer w0.305: 4.85,15.9 C113.1@6.548,15.9
N18038575: C3.2 L3.1 U1.15 | length 3.4
  Top Layer w0.203: U1.15@13.1,20.35 13.1,21.865 13.21,21.975 13.515,21.975 13.974,22.434 13.974,22.774 C3.2@14.25,23.05
N18038577: C4.2 L3.2 U1.16 | length 3.3
  Top Layer w0.203: C4.2@11.6,23.05 C4.2@11.625,23.05 11.88,22.795 11.88,22.45 12.185,22.145 12.185,21.975 12.48,21.975 12.605,21.85 12.6,21.845 U1.16@12.6,20.35
N18038619: C3.1 C5.1 L4.2 L6.2 U1.13 | length 7.8
  Top Layer w0.203: C5.1@13.191,23.742 13.209,23.742 13.222,23.755 13.222,23.742 13.325,23.638 C3.1@13.325,23.05 ; C3.1@13.275,23.075 C3.1@13.3,23.05 ; C5.1@13.275,23.875 13.5,24.1 v2(13.5,24.6) ; L6.2@13.525,25.15 13.5,25.125 v2(13.5,24.6) ; U1.13@14.1,20.35 14.1,20.975 v1(14.4,21.275) ; L4.2@14.475,24.81 14.265,24.6 v2(13.5,24.6)
  Signal Layer 3 w0.203: v2(13.5,24.6) v1(14.4,21.275)
N18038621: C4.1 C6.1 L5.2 L7.2 U1.14 | length 7.7
  Top Layer w0.203: L5.2@11.7,24.86 11.96,24.6 v2(12.675,24.6) ; C4.1@12.5,23.05 12.475,23.075 12.536,23.136 12.536,23.748 12.525,23.759 C6.1@12.525,23.875 12.675,24.025 v2(12.675,24.6) ; L7.2@12.65,25.15 12.675,25.125 v2(12.675,24.6) ; U1.14@13.6,20.35 v1(13.6,21)
  Signal Layer 3 w0.203: v2(12.675,24.6) v1(13.6,21)
N18038649: C7.1 C8.2 L6.1 | length 2.1
  Top Layer w0.203: L6.1@13.525,26.2 13.525,27.325 13.675,27.475 14.3,27.475 C8.2@14.375,27.4
N18038653: C7.2 C9.2 L7.1 | length 2
  Top Layer w0.203: C9.2@11.825,27.425 11.875,27.475 12.475,27.475 12.625,27.325 C7.2@12.625,26.95 12.65,26.925 L7.1@12.65,26.2
N18038740: C11.1 L8.1 L9.2 | length 1.5
  Top Layer w0.457: L8.1@15.975,30.35 C11.1@16.725,30.35 L9.2@17.475,30.35
N18038746: BAL1.1 C10.1 L8.2 | length 1.4
  Top Layer w0.457: BAL1.1@13.6,30.2 13.75,30.35 C10.1@14.225,30.35 L8.2@14.925,30.35
N18038850: BAL1.4 C8.1 | length 1
  Top Layer w0.203: BAL1.4@13.425,28.125 13.6,28.3 C8.1@14.375,28.3 C8.1@14.4,28.3
N18038856: BAL1.3 C9.1 | length 0.7
  Top Layer w0.203: C9.1@11.825,28.325 BAL1.3@12.5,28.325
PAVDD: L103.1 R210.1 R211.1 | length 12.9
  Top Layer w0.635: v1(6.2,21.9) v1(6.2,22.45) 6.2,22.95 L103.1@6.35,23.1
  Signal Layer 3 w0.635: v1(4.15,13.55) v1(4.15,14.15) 4.202,14.15 4.302,14.05 5.625,15.373 5.625,17.427 6.625,18.427 6.625,19.652 6.2,20.077 v1(6.2,21.9) v1(6.2,22.45)
  Bottom Layer w0.635: v1(4.15,14.15) v1(4.15,13.55) 4.15,13.225 R211.1@4.4,12.975
RADIO_#RESET: C207.1 P200.17 TPJ17.1 U1.12 | length 19.6
  Top Layer w0.127: U1.12@14.698,19.75 U1.12@14.7,19.752 ; U1.12@14.7,19.75 U1.12@14.7,19.752 ; v1(14.876,20.276) 14.7,20.1 U1.12@14.7,19.752
  Bottom Layer w0.102: P200.17@13.095,27.55 13.095,28.195 13.652,28.752 16.025,28.752 16.31,28.468 16.31,26.59 16.767,26.133 16.944,26.133 17.182,25.895 17.182,25.558 17.079,25.455 17.079,22.469 17.142,22.405 17.142,19.992 C207.1@15.525,18.375 ; v1(14.876,20.276) 14.876,19.024 C207.1@15.525,18.375 ; TPJ17.1@15.55,17.1 15.525,17.125 C207.1@15.525,18.375
RADIO_PA0: P200.19 P201.12 TPJ5.1 U1.25 | length 36.1
  Top Layer w0.127: v1@7.5,20 7.75,19.75 U1.25@8,19.75
  Signal Layer 3 w0.102: v1(7.3,20.1) 7.3,20.125 7.832,20.656 8.175,20.656 9.189,19.643 15.168,19.643 15.726,20.201 v1(15.726,21.551)
  Bottom Layer w0.102: v1(7.3,20.1) 6.892,19.692 6.892,19.233 8.025,18.1 8.025,15.3 7.278,14.553 7.278,9.082 7.796,8.564 7.798,8.564 9.125,7.237 P201.12@9.125,7.2 ; P201.12@9.285,6.45 P201.12@9.285,7.09 ; P200.19@14.365,27.55 14.365,26.885 15.469,25.781 16.144,25.781 16.497,25.428 16.497,23.547 15.726,22.776 v1(15.726,21.551) 15.726,19.876 TPJ5.1@15.55,19.7
RADIO_PA1: P200.20 P201.14 TPJ6.1 U1.26 | length 54.2
  Top Layer w0.127: v1(7.298,19.45) 7.498,19.25 U1.26@8,19.25
  Signal Layer 3 w0.102: v1(7.298,19.45) 8.488,19.45 8.702,19.236 15.695,19.236 17.186,17.745 18.746,17.745 18.991,17.5 v1(19.4,17.5) ; v1(19.038,22.813) 19.838,22.813 21.056,24.032 21.056,24.475 21.7,25.119 v1(21.7,25.225)
  Bottom Layer w0.102: v1(7.298,19.45) 8.25,18.498 8.25,15.238 7.481,14.469 7.481,9.166 7.88,8.768 7.882,8.768 8.95,7.7 10.025,7.7 P201.14@10.4,7.325 ; P200.20@14.365,29.736 P200.20@14.365,30.45 14.365,31.165 15.375,32.175 18.825,32.175 19.144,31.856 20.244,31.856 20.375,31.725 21.175,31.725 21.463,31.437 21.463,25.437 v1@21.7,25.2 ; TPJ6.1@19.02,22.07 19.02,22.006 20.337,20.689 20.337,18.499 19.4,17.562 v1(19.4,17.5) ; TPJ6.1@19.038,22.07 v1(19.038,22.813)
RADIO_PA2: P200.21 P201.3 TPJ7.1 U1.27 | length 48.2
  Top Layer w0.127: v1(4.825,19.625) 4.994,19.794 6.306,19.794 7.35,18.75 U1.27@8,18.75
  Signal Layer 3 w0.102: v1(4.825,19.625) 5.5,20.3 5.5,23.625 6.225,24.35 6.225,25.534 8.885,28.194 14.693,28.194 16.776,26.112 v1(16.776,25.726)
  Bottom Layer w0.102: P201.3@4.205,3.55 4.205,4.22 3.45,4.975 2.818,4.975 1.475,6.318 1.475,13.445 2.625,14.595 2.625,16.5 4.825,18.7 v1(4.825,19.625) ; P200.21@15.635,26.865 P200.21@15.635,26.965 ; P200.21@15.635,27.55 P200.21@15.635,26.965 ; TPJ7.1@16.49,22.03 16.706,22.246 16.7,22.253 16.776,22.329 v1(16.776,25.726) 16.776,25.824 P200.21@15.635,26.965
